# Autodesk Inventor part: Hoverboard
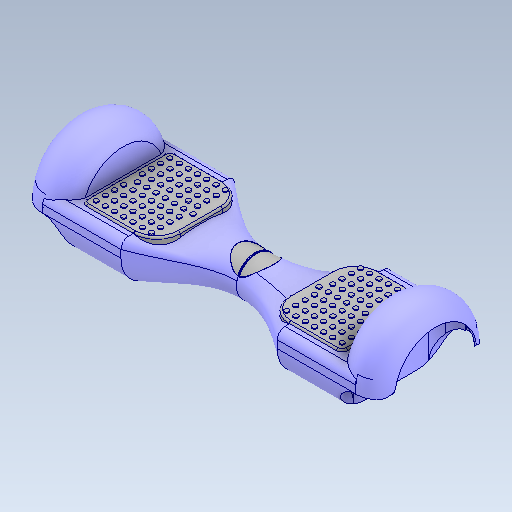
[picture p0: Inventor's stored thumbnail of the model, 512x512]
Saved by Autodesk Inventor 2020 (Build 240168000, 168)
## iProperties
Created: 2020-04
Part Number: Hoverboard
Material: Générique
Document SubType Name: Modeling
Designer: bruno
Density: 1 g/cm^3
Appearance: Par défaut
Sending System: SolidWorks 2017
Last Author: hpras
Last Saved: 2020-04-23
Author: bruno
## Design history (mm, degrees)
mirror "Mirror4"
sketch "Esquisse1"
  geometry: L1 (-61.958, 33.92)-(-63.746, -0.188) reference; L2 (-53.301, 36.732)-(-31.808, 10.19) reference; L3 (-49.437, 42.051)-(-17.552, 29.811) reference; L4 (-49.437, 51.153)-(-17.552, 63.393) reference; L5 (-53.301, 56.472)-(-31.808, 83.015) reference; L6 (-61.958, 59.285)-(-63.746, 93.392) reference; L7 (-68.211, 57.253)-(-86.812, 85.897) reference; L8 (-76.179, 50.591)-(-106.551, 58.729) reference; L9 (-76.179, 42.614)-(-106.551, 34.475) reference; L10 (-68.211, 35.951)-(-86.812, 7.307) reference; C1 r 12.7 at (-61.294, 46.602); A1 r 49.95 centre (-61.294, 46.602) between (-85.766, 3.058) and (-67.09, -3.01) reference; A2 r 3 centre (-66.742, -0.031) between (-67.09, -3.01) and (-63.746, -0.188) reference; A3 r 12.7 centre (-61.294, 46.602) between (-61.958, 33.92) and (-53.301, 36.732) reference; A4 r 3 centre (-29.476, 12.078) between (-31.808, 10.19) and (-27.443, 9.872) reference; A5 r 49.95 centre (-61.294, 46.602) between (-27.443, 9.872) and (-15.9, 25.759) reference; A6 r 3 centre (-18.627, 27.01) between (-15.9, 25.759) and (-17.552, 29.811) reference; A7 r 12.7 centre (-61.294, 46.602) between (-49.437, 42.051) and (-49.437, 51.153) reference; A8 r 3 centre (-18.627, 66.194) between (-17.552, 63.393) and (-15.9, 67.446) reference; A9 r 49.95 centre (-61.294, 46.602) between (-15.9, 67.446) and (-27.443, 83.333) reference; A10 r 3 centre (-29.476, 81.127) between (-27.443, 83.333) and (-31.808, 83.015) reference; A11 r 12.7 centre (-61.294, 46.602) between (-53.301, 56.472) and (-61.958, 59.285) reference; A12 r 3 centre (-66.742, 93.235) between (-63.746, 93.392) and (-67.09, 96.215) reference; A13 r 49.95 centre (-61.294, 46.602) between (-67.09, 96.215) and (-85.766, 90.146) reference; A14 r 3 centre (-84.296, 87.531) between (-85.766, 90.146) and (-86.812, 85.897) reference; A15 r 12.7 centre (-61.294, 46.602) between (-68.211, 57.253) and (-72.707, 52.173) reference; A16 r 3 centre (-75.403, 53.489) between (-76.179, 50.591) and (-72.707, 52.173) reference; A17 r 3 centre (-107.328, 55.831) between (-106.551, 58.729) and (-110.269, 56.421) reference; A18 r 49.95 centre (-61.294, 46.602) between (-110.269, 56.421) and (-110.269, 36.784) reference; A19 r 3 centre (-107.328, 37.373) between (-110.269, 36.784) and (-106.551, 34.475) reference; A20 r 3 centre (-75.403, 39.716) between (-72.707, 41.032) and (-76.179, 42.614) reference; A21 r 12.7 centre (-61.294, 46.602) between (-72.707, 41.032) and (-68.211, 35.951) reference; A22 r 3 centre (-84.296, 5.673) between (-86.812, 7.307) and (-85.766, 3.058) reference; 11 further points
  constraints: 1 centre point, 1 coincident
extrude "Extrusion1" cut sketch "Esquisse1" distance "d0" = 10; taper "d1" = 0 deg
sketch "Esquisse2"
  geometry: C1 r 12.7 at (-61.294, 46.602) reference; 1 further point
extrude "Extrusion2" cut sketch "Esquisse2" distance "d2" = 10; taper "d3" = 0 deg
node "Solide1"
node "Référence1"
